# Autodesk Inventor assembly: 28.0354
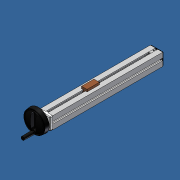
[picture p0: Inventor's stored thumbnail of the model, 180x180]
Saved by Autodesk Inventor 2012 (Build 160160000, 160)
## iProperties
Created: 2011-09
Part Number: 28.0354
Document SubType Name: Assembly
Designer: Administrator
Description: MINI ADJ UNIT 45X45
Author: Administrator
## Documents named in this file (8)
- C:\Andys Backup Data\ANDY'S INVENTOR\INVENTOR LIBRARIES\PARTS LIBRARY\READY FOR USE MODULES LG\28.0354 MINI ADJ UNIT 45X45.iam
- C:\Andys Backup Data\ANDY'S INVENTOR\INVENTOR LIBRARIES\PARTS LIBRARY\READY FOR USE MODULES LG\SUBCOMPONENTS\28.0354_1 MINI ADJ 45X45 PROFILE.ipt
- C:\Andys Backup Data\ANDY'S INVENTOR\INVENTOR LIBRARIES\PARTS LIBRARY\READY FOR USE MODULES LG\SUBCOMPONENTS\28.0368 MINI ADJ BEARING SUPPORT 45X45.ipt
- C:\Andys Backup Data\ANDY'S INVENTOR\INVENTOR LIBRARIES\PARTS LIBRARY\FASTENING ELEMENTS\SCREWS CAP\21.1200 M8X16.ipt
- C:\Andys Backup Data\ANDY'S INVENTOR\INVENTOR LIBRARIES\PARTS LIBRARY\READY FOR USE MODULES LG\28.0350 MINI ADJ UNIT FITTING KIT.iam
- C:\Andys Backup Data\ANDY'S INVENTOR\INVENTOR LIBRARIES\PARTS LIBRARY\END CAPS\22.1004_1 END CAP 45X45 GRAY.iam
- C:\Andys Backup Data\ANDY'S INVENTOR\INVENTOR LIBRARIES\PARTS LIBRARY\READY FOR USE MODULES LG\SUBCOMPONENTS\28.0212 HANDWHEEL 80mm.iam
- C:\Andys Backup Data\ANDY'S INVENTOR\INVENTOR LIBRARIES\PARTS LIBRARY\READY FOR USE MODULES LG\SUBCOMPONENTS\19.0100_6 BUSHING.ipt
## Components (7 placed, 7 different names)
1. 28.0354_1 MINI ADJ 45X45 PROFILE:1 — Angle:1, Mate:1, Flush:2, Mate:2, Flush:3, Flush:4, Flush:5
2. 28.0368 MINI ADJ BEARING SUPPORT 45X45:1 — Mate:1, Insert:4, Flush:2, Insert:5, Flush:5
3. 21.1200 M8 x 16:1 — Insert:4
4. 28.0350 MINI ADJ UNIT FITTING KIT:1 [sub-assembly] — Angle:1, Insert:5, Mate:5, Mate:8
5. 22.1004\1 END CAP 45X45 GRAY:1 [sub-assembly] — Mate:2, Flush:3, Flush:4
6. 28.0212 HANDWHEEL 80mm:1 [sub-assembly] — Mate:5, Angle:2, Mate:6, Mate:7
7. 19.0100_6 BUSHING:1 — Angle:2, Mate:6, Mate:7, Mate:8
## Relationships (14: Mate 6, Flush 4, Angle 2, Insert 2)
- Angle:1: 28.0354_1 MINI ADJ 45X45 PROFILE:1 ↔ 28.0350 MINI ADJ UNIT FITTING KIT:1
- Mate:1: 28.0354_1 MINI ADJ 45X45 PROFILE:1 ↔ 28.0368 MINI ADJ BEARING SUPPORT 45X45:1
- Insert:4: 28.0368 MINI ADJ BEARING SUPPORT 45X45:1 ↔ 21.1200 M8 x 16:1
- Flush:2: 28.0354_1 MINI ADJ 45X45 PROFILE:1 ↔ 28.0368 MINI ADJ BEARING SUPPORT 45X45:1
- Mate:2: 28.0354_1 MINI ADJ 45X45 PROFILE:1 ↔ 22.1004\1 END CAP 45X45 GRAY:1
- Flush:3: 28.0354_1 MINI ADJ 45X45 PROFILE:1 ↔ 22.1004\1 END CAP 45X45 GRAY:1
- Flush:4: 28.0354_1 MINI ADJ 45X45 PROFILE:1 ↔ 22.1004\1 END CAP 45X45 GRAY:1
- Insert:5: 28.0368 MINI ADJ BEARING SUPPORT 45X45:1 ↔ 28.0350 MINI ADJ UNIT FITTING KIT:1
- Mate:5: 28.0350 MINI ADJ UNIT FITTING KIT:1 ↔ 28.0212 HANDWHEEL 80mm:1
- Flush:5: 28.0354_1 MINI ADJ 45X45 PROFILE:1 ↔ 28.0368 MINI ADJ BEARING SUPPORT 45X45:1
- Angle:2: 28.0212 HANDWHEEL 80mm:1 ↔ 19.0100_6 BUSHING:1
- Mate:6: 28.0212 HANDWHEEL 80mm:1 ↔ 19.0100_6 BUSHING:1
- Mate:7: 28.0212 HANDWHEEL 80mm:1 ↔ 19.0100_6 BUSHING:1
- Mate:8: 28.0350 MINI ADJ UNIT FITTING KIT:1 ↔ 19.0100_6 BUSHING:1
